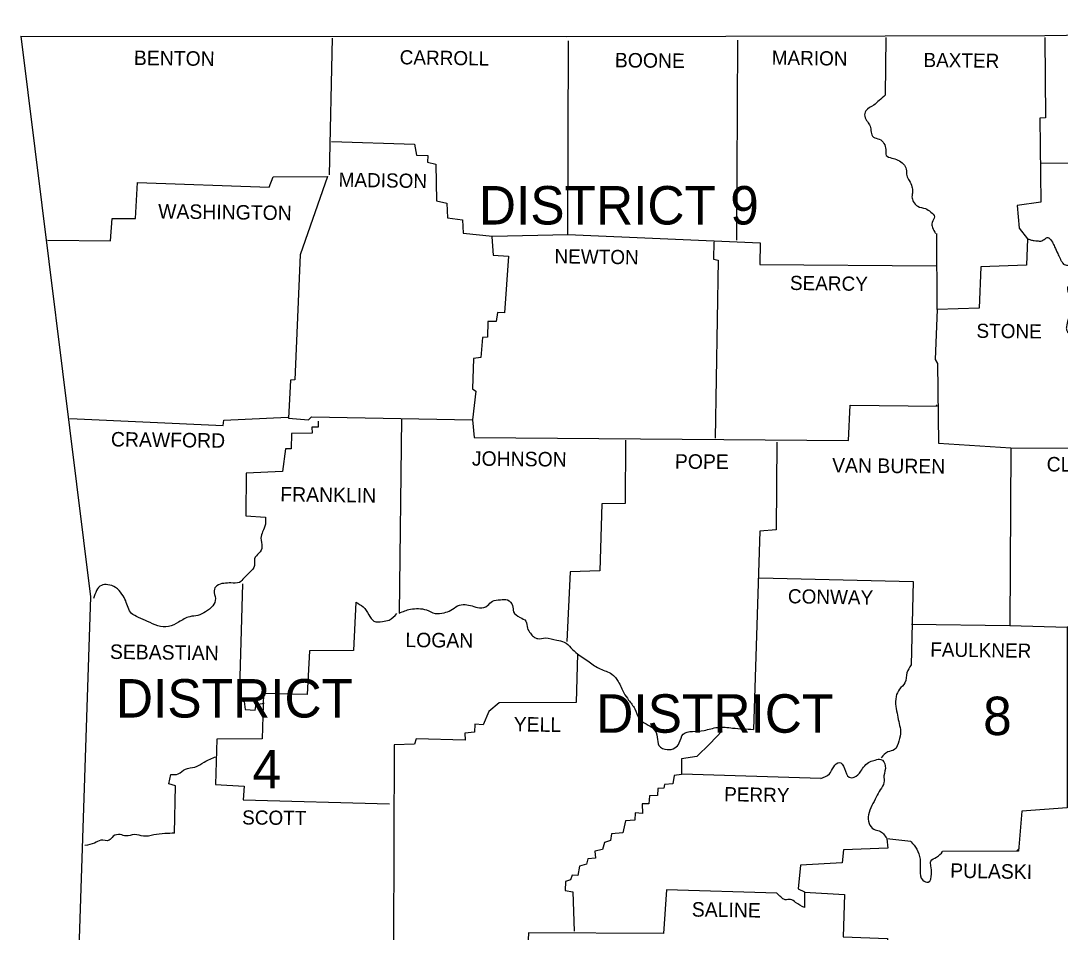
# Model space of a CAD drawing. Extents: x 3046 to 131673, y -8885 to 10756.
# Drawn here: x 25766 to 28781, y 7714 to 10358 of the extents above; entities that cross this region are included whole.
import ezdxf

# ---------------------------------------------------------------- set-up
doc = ezdxf.new("R2010")
doc.units = 0
for name, color, linetype in [('1', 7, 'Continuous'), ('2', 7, 'Continuous'), ('3', 7, 'Continuous')]:
    doc.layers.add(name, color=color, linetype=linetype)

msp = doc.modelspace()

# ---------------------------------------------------------------- linework, layer by layer
at = {"layer": '1'}
for points in [[(25766.1, 10313), (27348.2, 10312), (28736.6, 10314.9), (30374.4, 10340.4), (31133.7, 10358)], [(25766.1, 10313), (25968.7, 8686.9), (25880.6, 6032.5)], [(29565.2, 10327.8), (29567.2, 10081.1), (29440, 10074.3), (29436.1, 9941.2), (28723.5, 9945.1)], [(26669.2, 10307.1), (26660.4, 9910.9)], [(26667.2, 10007.7), (26907.9, 9999.9), (26913.8, 9968.6), (26947.1, 9967.6), (26946.1, 9948), (26969.6, 9942.2), (26971.5, 9835.5), (27001.9, 9828.7), (27003.8, 9786.6), (27046.9, 9780.7), (27048.8, 9741.6), (27133.9, 9732.8), (27353.1, 9737.7), (27355.1, 10300.3)], [(27845.2, 10302.2), (27842.3, 9721.1)], [(28275.7, 10309.1), (28273.8, 10141.8)], [(28736.6, 10309.1), (28738.5, 10076.2), (28721.9, 10075.2), (28724.8, 9831.6), (28656.3, 9821.8), (28662.2, 9756.3), (28685.7, 9725.9), (28683.7, 9648.7), (28550.7, 9643.8), (28545.8, 9524.4), (28424.5, 9520.5), (28418.6, 9375.7), (28425.4, 9363.9), (28428.4, 9133), (28637.7, 9119.3), (28634.8, 8603.7), (28801.1, 8598.8), (28801.1, 8074.4), (28670, 8064.6), (28660.3, 7949.2), (28440.1, 7948.2)], [(25843.4, 9721.1), (26026.4, 9720.1), (26031.3, 9784.6), (26098.8, 9784.6), (26104.7, 9889.3), (26486.2, 9875.6), (26498, 9905), (26655.5, 9906), (26576.2, 9679), (26560.6, 9316), (26548.9, 9315), (26543, 9205.4), (26600.7, 9200.5), (26609.5, 9209.3), (27076.2, 9200.5), (27081.1, 9148.7)], [(28424.5, 9520.5), (28423.5, 9740.6)], [(27132, 9730.8), (27135.9, 9678), (27180.9, 9675.1), (27169.2, 9510.7), (27148.6, 9511.7), (27144.7, 9485.3), (27121.2, 9485.3), (27120.2, 9440.2), (27105.6, 9439.3), (27100.7, 9381.5), (27079.1, 9378.6), (27076.2, 9290.6), (27086, 9283.7), (27076.2, 9200.5)], [(27353.1, 9737.7), (27910.8, 9714.2), (27909.8, 9650.6), (28421.5, 9646.7)], [(27776.8, 9717.1), (27775.8, 9666.3), (27788.5, 9663.3), (27780.7, 9146.7)], [(27081.1, 9148.7), (28167.1, 9139.9), (28172, 9242.6), (28424.5, 9239.7)], [(28421.5, 9240.7), (28424.5, 9243.6)], [(25908, 9204.5), (26353.2, 9183.9), (26355.1, 9199.6), (26541, 9208.4)], [(26629.1, 9196.6), (26629.1, 9179), (26610.5, 9179), (26611.5, 9161.4), (26551.8, 9160.4), (26550.8, 9116.4), (26534.2, 9116.4), (26525.4, 9050.8), (26419.7, 9046), (26418.7, 8921.7), (26475.5, 8917.8)], [(26870.7, 9204.5), (26863.9, 8639.9)], [(27520.4, 9140.9), (27519.4, 8957.9), (27451.9, 8956.9), (27446, 8762.2), (27359.9, 8759.3), (27350.2, 8557.7)], [(27958.7, 9136), (27956.8, 8881.6), (27909.8, 8877.7), (27891.2, 8302.4)], [(28637.7, 9119.3), (29140.6, 9116.4), (29183.7, 9136.9), (29180.8, 8754.4), (29151.4, 8741.7), (29125, 8719.2), (29116.2, 8710.4), (29115.2, 8600.8), (28801.1, 8598.8)], [(26408.9, 8724.1), (26399.2, 8387.5), (26413.8, 8383.6), (26416.8, 8360.1), (26446.1, 8358.1), (26449.1, 8374.8), (26472.5, 8378.7)], [(27907.9, 8741.7), (28355, 8730.9), (28349.1, 8489.2)], [(26737.7, 8671.2), (26730.8, 8531.3), (26603.6, 8530.3), (26596.8, 8403.1), (26470.6, 8406.1), (26466.7, 8275), (26334.6, 8274), (26330.7, 8142.9), (26413.8, 8138), (26410.9, 8097.9), (26835.5, 8086.1)], [(28350.1, 8607.6), (28634.8, 8603.7)], [(27380.5, 8521.5), (27376.6, 8380.6), (27153.5, 8379.7), (27124.2, 8354.2), (27107.5, 8315.1), (27083.1, 8317), (27082.1, 8294.5), (27053.7, 8291.6), (27054.7, 8271.1), (26912.8, 8275), (26907.9, 8259.3), (26849.2, 8257.4), (26847.3, 7685)], [(27800.2, 8298.4), (27765, 8260.3), (27726.9, 8224.1), (27682.8, 8217.2), (27682.8, 8171.3), (27661.3, 8168.3), (27657.4, 8144.8), (27632.9, 8142.9), (27631, 8132.1), (27614.3, 8131.1), (27613.4, 8110.6), (27589.9, 8109.6), (27587.9, 8086.1), (27568.4, 8086.1), (27569.3, 8058.7), (27547.8, 8060.7), (27546.8, 8039.2), (27520.4, 8037.2), (27512.6, 8002), (27479.3, 7999.1), (27476.4, 7979.5), (27458.8, 7974.6), (27453.9, 7954), (27431.4, 7949.2), (27433.3, 7928.6), (27410.8, 7926.7), (27406.9, 7911), (27386.4, 7905.1), (27381.5, 7878.7), (27365.8, 7879.7), (27360.9, 7866), (27346.3, 7861.1), (27345.3, 7834.7), (27367.8, 7830.8), (27371.7, 7717.3)], [(26212.3, 8001), (26215.2, 8139), (26195.6, 8144.8), (26201.5, 8171.3)], [(28086.9, 8159.5), (27683.8, 8172.2)], [(28348.1, 7976.6), (28277.7, 7984.4), (28280.6, 7958), (28152.5, 7953.1), (28148.5, 7914.9), (28028.2, 7908.1), (28021.4, 7839.6), (28039, 7830.8), (28039, 7785.8)], [(28655.4, 7950.1), (28660.3, 7955)], [(27958.7, 7826.9), (27638.8, 7836.6), (27630, 7710.4), (27238.6, 7712.4), (27236.7, 7670.3)], [(28039, 7830.2), (28155.4, 7822.9), (28151.5, 7700.6), (28279.7, 7695.8), (28281.6, 7589.1), (28342.3, 7584.2), (28342.3, 7565.6), (28399, 7561.7), (28401, 7493.2), (28530.1, 7493.2), (28534, 7425.7), (28653.4, 7419.8), (28652.4, 7292.5)]]:
    msp.add_lwpolyline(points, dxfattribs=at)
for points in [[(28273.8, 10141.8), (28256.2, 10127.1), (28240.5, 10113.4), (28217, 10096.8), (28214.1, 10081.1), (28221.9, 10065.5), (28229.8, 10052.7), (28232.7, 10035.1), (28239.5, 10020.4), (28256.2, 10014.6), (28269.9, 10001.9), (28274.8, 9984.2), (28276.7, 9967.6), (28292.4, 9959.8), (28310, 9953.9), (28326.6, 9942.2), (28334.4, 9927.5), (28336.4, 9908.9), (28343.2, 9894.2), (28351.1, 9876.6), (28353, 9861.9), (28351.1, 9847.3), (28355, 9833.6), (28367.7, 9819.9), (28390.2, 9813), (28405.9, 9803.2), (28416.6, 9789.5), (28409.8, 9772.9), (28410.8, 9758.2), (28419.6, 9740.6)], [(28685.7, 9725.9), (28695.3, 9722.3), (28705.1, 9720.3), (28715, 9719.5), (28724.8, 9719.1), (28730.9, 9721.1), (28737, 9725.5), (28742.8, 9728.9), (28745.6, 9729.2), (28748.3, 9727.9), (28753.9, 9722.3), (28758.2, 9716), (28761.7, 9709.3), (28764.9, 9702.5), (28773.7, 9682.9), (28780.5, 9668.5), (28784.3, 9661.4), (28786.3, 9657.9), (28788.4, 9654.5), (28793, 9650.8), (28799.2, 9649.2), (28805.8, 9648), (28809, 9647.1), (28811.9, 9645.7), (28829.5, 9630.1), (28832, 9621.6), (28831.4, 9617.2), (28829.5, 9613.4), (28825.8, 9609.4), (28821.8, 9605.6), (28817.7, 9601.8), (28813.9, 9597.8), (28812.1, 9595.9), (28806.5, 9590.4), (28803.5, 9586.5), (28802.6, 9584.4), (28802.1, 9582.1), (28802.4, 9577.5), (28803.5, 9572.9), (28804.9, 9568.2), (28806, 9563.5), (28808.1, 9550.8), (28809.9, 9538.1), (28809.9, 9513.6), (28804.1, 9491.1), (28799.2, 9470.6), (28798.7, 9466.1), (28799.3, 9461.7), (28801.1, 9457.3), (28802.4, 9455.1), (28804.1, 9453), (28806.1, 9451.3), (28808.3, 9450.5), (28813.3, 9451.2), (28822.7, 9455.9), (28827.6, 9459.4), (28832.2, 9463.6), (28837, 9467.7), (28842.2, 9470.6), (28847.2, 9471.8), (28852.5, 9472.3), (28862.8, 9470.6), (28872.8, 9465.7), (28882.4, 9459.8), (28887.6, 9454.9), (28892.2, 9449), (28897.1, 9443.8), (28899.8, 9442.1), (28901.3, 9441.5), (28902.9, 9441.2), (28913.1, 9442.2), (28923.4, 9445.1), (28940.1, 9450), (28963.6, 9456.9), (28980.2, 9448.1), (28994.9, 9436.3), (28999.4, 9431.8), (29003.6, 9427), (29007.9, 9422.2), (29012.5, 9417.7), (29029.1, 9406), (29050.6, 9395.2), (29057.1, 9393.1), (29063.7, 9391.7), (29070.4, 9390.3), (29077.1, 9388.4), (29090.9, 9382.4), (29096.9, 9377.9), (29099.4, 9375.1), (29100.5, 9373.5), (29101.5, 9371.8), (29103.1, 9368.2), (29105.5, 9357.6), (29105.7, 9350.5), (29105.4, 9343.4), (29104.4, 9318.9), (29102.5, 9288.6), (29100.5, 9255.3), (29100.1, 9247.2), (29100.2, 9239.1), (29101.1, 9231), (29102.1, 9227), (29103.5, 9223), (29108.6, 9212), (29114.2, 9201.5), (29121.2, 9189), (29127.9, 9176.1), (29131, 9164.5), (29131.5, 9158.6), (29131.8, 9152.6), (29132.3, 9134.5), (29131, 9116.5)], [(26475.5, 8917.8), (26475.5, 8897.2), (26467.6, 8875.7), (26462.8, 8857.1), (26465.7, 8832.7), (26456.9, 8813.1), (26444.2, 8797.4), (26444.2, 8777.9), (26429.5, 8757.3), (26413.8, 8741.7), (26400.1, 8728.9), (26375.7, 8727), (26355.1, 8726), (26334.6, 8719.2), (26326.8, 8704.5), (26330.7, 8682), (26322.8, 8660.5), (26302.3, 8643.8), (26279.8, 8633.1), (26256.3, 8629.2), (26224, 8613.5), (26194.7, 8600.8), (26163.4, 8602.7), (26134, 8615.5), (26107.6, 8627.2), (26087, 8638.9), (26070.4, 8675.1), (26059.6, 8694.7), (26041.1, 8714.3), (26018.6, 8722.1), (26000, 8720.1), (25977.5, 8682)], [(26737.7, 8671.2), (26759.2, 8657.5), (26775.8, 8635), (26790.5, 8616.4), (26815, 8615.5), (26834.5, 8619.4), (26857, 8638.9)], [(26863.9, 8639.9), (26896.2, 8650.7), (26919.7, 8652.6), (26943.1, 8648.7), (26967.6, 8638.9), (26994, 8640.9), (27013.6, 8647.7), (27033.2, 8660.5), (27054.7, 8664.4), (27075.2, 8660.5), (27096.8, 8654.6), (27120.2, 8661.4), (27133.9, 8674.2), (27157.4, 8678.1), (27178, 8678.1), (27192.6, 8661.4), (27195.6, 8643.8), (27214.2, 8627.2), (27230.8, 8616.4), (27235.7, 8595.9), (27244.5, 8581.2), (27253.3, 8571.4), (27266, 8565.6), (27287.5, 8567.5), (27320.8, 8560.7), (27342.3, 8555.8), (27361.9, 8539.1), (27380.5, 8521.5)], [(27380.5, 8521.5), (27414.7, 8498), (27447, 8477.5), (27480.3, 8462.8), (27498.9, 8441.3), (27515.5, 8408), (27529.2, 8387.5), (27546.8, 8362), (27559.5, 8333.7), (27580.1, 8318), (27601.6, 8304.3), (27612.4, 8279.9), (27617.3, 8255.4), (27640.8, 8243.7), (27663.3, 8248.5), (27676, 8263.2), (27687.7, 8288.7), (27714.1, 8296.5), (27748.4, 8299.4), (27787.5, 8308.2), (27830.6, 8306.3), (27891.2, 8302.4)], [(28349.1, 8489.2), (28336.4, 8466.7), (28330.5, 8437.4), (28314.9, 8418.8), (28305.1, 8397.3), (28304.1, 8368.9), (28309, 8343.5), (28313.9, 8319), (28317.8, 8296.5), (28312.9, 8268.1), (28300.2, 8243.7), (28280.6, 8236.8), (28262, 8220.2)], [(26201.5, 8171.3), (26223, 8173.2), (26243.6, 8186.9), (26271, 8192.8), (26298.4, 8207.5), (26332.6, 8223.1)], [(28086.9, 8159.5), (28111.4, 8173.2), (28124.1, 8193.8), (28139.7, 8206.5), (28155.4, 8188.9), (28169.1, 8163.4), (28183.8, 8163.4), (28202.4, 8181), (28214.1, 8196.7), (28228.8, 8208.4), (28244.4, 8213.3), (28261.1, 8215.3), (28273.8, 8196.7), (28269.9, 8167.3), (28269.9, 8147.8), (28259.1, 8127.2), (28247.4, 8105.7), (28234.6, 8081.2), (28224.9, 8054.8), (28226.8, 8029.4), (28240.5, 8012.8), (28256.2, 8007.9), (28277.7, 7986.3)], [(26212.3, 8001), (26183.9, 8000), (26151.6, 7996.1), (26122.3, 7992.2), (26095.8, 7997.1), (26071.4, 7993.2), (26054.8, 7997.1), (26034.2, 7992.2), (26022.5, 7980.5), (25998, 7980.5), (25980.4, 7972.6), (25952, 7965.8)], [(28348.1, 7976.6), (28364.8, 7955), (28374.6, 7925.7), (28374.6, 7892.4), (28382.4, 7865), (28398, 7859.1), (28407.8, 7882.6), (28405.9, 7906.1), (28405.9, 7919.8), (28422.5, 7931.5), (28440.1, 7948.2)], [(28039, 7785.8), (28013.5, 7800.4), (27998.8, 7809.2), (27983.2, 7808.3), (27970.5, 7816.1), (27958.7, 7826.9)]]:
    msp.add_spline(points, degree=3, dxfattribs=at)

# ---------------------------------------------------------------- texts
at = {"layer": '2'}
for s, height, rotation, p in [('BENTON', 42.07, 359.2527, (26093.9, 10229.8)), ('CARROLL', 41.09, 359.1481, (26864.9, 10231.8)), ('BOONE', 42.07, 359.4001, (27489.1, 10223)), ('MARION', 41.09, 359.1854, (27944.1, 10230.8)), ('BAXTER', 41.09, 359.2559, (28384.3, 10224)), ('MADISON', 41.09, 359.0906, (26687.8, 9876.6)), ('WASHINGTON', 42.06, 359.232, (26164.3, 9784.6)), ('NEWTON', 41.09, 359.2717, (27314, 9654.5)), ('SEARCY', 41.08, 359.2527, (27996.9, 9577.2)), ('STONE', 41.08, 359.4001, (28538, 9438.3)), ('CRAWFORD', 42.06, 359.2771, (26027.4, 9123.2)), ('JOHNSON', 42.07, 359.3514, (27074.3, 9067.5)), ('POPE', 42.07, 359.6155, (27663.3, 9058.7)), ('VAN BUREN', 42.07, 359.3508, (28119.2, 9047.9)), ('CLEBURNE', 42.06, 359.2535, (28741.5, 9050.8)), ('FRANKLIN', 42.07, 359.1815, (26518.5, 8963.8)), ('CONWAY', 41.08, 359.0371, (27991, 8668.3)), ('LOGAN', 42.07, 359.3969, (26881.5, 8541.1)), ('SEBASTIAN', 42.06, 359.2816, (26024.4, 8506.8)), ('FAULKNER', 41.09, 359.2486, (28403.9, 8513.7)), ('YELL', 42.07, 359.1987, (27195.6, 8296.5)), ('PERRY', 41.09, 359.0858, (27806.1, 8094)), ('SCOTT', 41.09, 359.4063, (26408, 8026.5)), ('PULASKI', 42.07, 359.053, (28461.6, 7871.9)), ('SALINE', 42.07, 359.1491, (27712.2, 7759.3))]:
    msp.add_text(s, height=height, rotation=rotation, dxfattribs=at).set_placement(p)
at = {"layer": '3'}
for s, height, p in [('DISTRICT 9', 111.54, (27094.8, 9767)), ('DISTRICT', 111.54, (26042, 8336.6)), ('DISTRICT', 111.54, (27435.3, 8292.6)), ('8', 111.5, (28557.5, 8285.7)), ('4', 111.5, (26438.3, 8131.1))]:
    msp.add_text(s, height=height, dxfattribs=at).set_placement(p)

doc.saveas('drawing.dxf')
